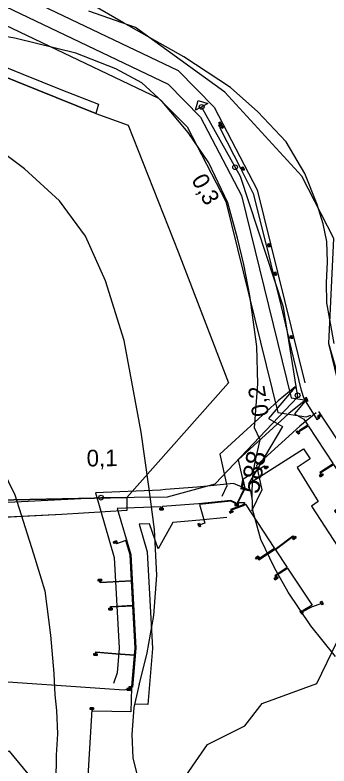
# Model space of a CAD drawing. Extents: x -709418 to -703832, y -1161719 to -1157826.
# Drawn here: x -705275.7 to -705143.5, y -1159799.2 to -1159483.1 of the extents above; entities that cross this region are included whole.
import ezdxf

# ---------------------------------------------------------------- set-up
doc = ezdxf.new("R2010")
doc.units = 0
for name, color, linetype in [('102_obvod PÚ', 7, 'Continuous'), ('103_hranice KÚ', 7, 'Continuous'), ('120_vrstevnice hlavní', 7, 'Continuous'), ('121_vrstevnice hlavní_popis', 7, 'Continuous'), ('122_vrstevnice základní', 7, 'Continuous'), ('201_orná půda_KN', 7, 'Continuous'), ('301_polní cesta_stav', 7, 'Continuous'), ('311_polní cesta_staničení', 7, 'Continuous'), ('609_LBC_stav', 7, 'Continuous'), ('611_LBK_stav', 7, 'Continuous'), ('708_el NN nadzemní a podzemní_ E.ON', 7, 'Continuous'), ('735_OP sítí TI', 7, 'Continuous'), ('Trasa-Hlavni  staniceni', 7, 'Continuous')]:
    doc.layers.add(name, color=color, linetype=linetype)

# ---------------------------------------------------------------- blocks, each defined once
blk = doc.blocks.new('Elektro - Implicitní$0$NN6301')
for points in [[(0, -0.7), (-0.7, 0)], [(-0.7, -0.7), (-0.7, 0), (0.7, 0), (0.7, -0.7)], [(-0.7, -0.7), (0.7, -0.7)], [(0, -0.7), (0.7, 0)]]:
    blk.add_lwpolyline(points)
blk = doc.blocks.new('Elektro - Implicitní$0$NN6201')
for points in [[(0.75, 0), (-0.75, 0)], [(-0.75, 0), (-0.75, -0.75)], [(0.75, -0.75), (0.75, 0)], [(-0.75, -0.75), (0.75, -0.75)], [(0.37, -0.18), (-0.38, -0.18)], [(-0.38, -0.18), (-0.38, -0.56)], [(-0.38, -0.56), (0.37, -0.56)], [(0.32, -0.23), (-0.33, -0.23)], [(-0.33, -0.23), (-0.33, -0.51)], [(-0.33, -0.51), (0.32, -0.51)], [(0.27, -0.27), (-0.28, -0.27)], [(-0.28, -0.27), (-0.28, -0.46)], [(-0.28, -0.46), (0.27, -0.46)], [(0.23, -0.32), (-0.23, -0.32)], [(-0.23, -0.32), (-0.23, -0.42)], [(-0.23, -0.42), (0.23, -0.42)], [(-0.19, -0.37), (0.19, -0.37)], [(0.23, -0.42), (0.23, -0.32)], [(0.27, -0.46), (0.27, -0.27)], [(0.32, -0.51), (0.32, -0.23)], [(0.37, -0.56), (0.37, -0.18)]]:
    blk.add_lwpolyline(points)
blk = doc.blocks.new('_kolecko-HB')
blk.add_circle((0, 0), 0.5)

msp = doc.modelspace()

# ---------------------------------------------------------------- linework, layer by layer
at = {"layer": '102_obvod PÚ'}
msp.add_lwpolyline([(-705337.11, -1159477.31), (-705321.2, -1159485.73), (-705305.28, -1159494.51), (-705288.87, -1159501.36), (-705272.46, -1159507.98), (-705256.4, -1159514.47), (-705240.56, -1159520.54), (-705241.7, -1159524.46), (-705228, -1159529.46), (-705206.95, -1159582.76), (-705185.79, -1159637.83), (-705228.59, -1159686.2), (-705228.61, -1159691.6), (-705256.06, -1159693.33), (-705338.98, -1159697.33), (-705340.61, -1159703.8), (-705368.6, -1159692.83), (-705394.93, -1159695.05), (-705422.83, -1159640.31), (-705432.68, -1159637.1), (-705471.87, -1159535.22), (-705499.42, -1159485.62), (-705524.82, -1159460.29)], dxfattribs=at)
at = {"layer": '103_hranice KÚ'}
msp.add_lwpolyline([(-705134.24, -1159654.08), (-705143.62, -1159621.36), (-705141.48, -1159577.11), (-705155, -1159550.95), (-705187.39, -1159515.59), (-705225.01, -1159488.33), (-705244.62, -1159481.43)], dxfattribs=at)
at = {"layer": '120_vrstevnice hlavní'}
for points in [[(-705223.36, -1159764.63), (-705220.12, -1159751.46), (-705217.29, -1159735.83), (-705216.04, -1159718.88), (-705216.95, -1159699.6), (-705219.35, -1159681.52), (-705222.58, -1159658.66), (-705229.69, -1159620.01), (-705237.57, -1159595), (-705246.09, -1159576.18), (-705257.01, -1159561.22), (-705271.76, -1159547.82), (-705285.35, -1159537.74), (-705305.1, -1159527.1), (-705322.99, -1159517.93), (-705362.53, -1159497), (-705381.94, -1159487.18), (-705402.79, -1159477.04)], [(-705223.39, -1159764.75), (-705225.66, -1159774.48), (-705226.57, -1159785.92), (-705226.11, -1159795.66), (-705224.32, -1159803.18), (-705221.95, -1159807.63), (-705216.68, -1159812.95), (-705208.68, -1159818.12), (-705200.49, -1159821.92), (-705193.33, -1159824), (-705183.78, -1159825.93), (-705174.04, -1159826.49), (-705160.04, -1159827.58), (-705145.01, -1159828.68), (-705126.77, -1159829.29)]]:
    msp.add_lwpolyline(points, dxfattribs=at)
msp.add_open_spline([(-705223.39, -1159764.75), (-705223.36, -1159764.63)], degree=1, dxfattribs=at)
at = {"layer": '122_vrstevnice základní'}
for points in [[(-705184.99, -1159513.55), (-705204.6, -1159500.63), (-705230, -1159486.31), (-705259.87, -1159468.99), (-705280, -1159460.17), (-705296.39, -1159454.1), (-705322.61, -1159446.57), (-705350.78, -1159437.2), (-705372.8, -1159429.22), (-705402.11, -1159420.31), (-705420.38, -1159413.38), (-705436.75, -1159405.26), (-705449.37, -1159398.53), (-705474.22, -1159384.97), (-705486.15, -1159376.87), (-705490.06, -1159372.24), (-705491.08, -1159370.18)], [(-705140.71, -1159753.08), (-705151.19, -1159740.1), (-705160.76, -1159725.96), (-705166.42, -1159715.8), (-705172.27, -1159703.79), (-705175.78, -1159691.08), (-705175.88, -1159683.03), (-705175.47, -1159675.64), (-705174.25, -1159669.85), (-705172.5, -1159661.94), (-705174.91, -1159656.77), (-705173.46, -1159638.29), (-705173.85, -1159622.6), (-705176.8, -1159601.16), (-705179.31, -1159588.1), (-705182.08, -1159577.04), (-705186.11, -1159562.15), (-705194.03, -1159545.31), (-705202.85, -1159532.45), (-705213.73, -1159519.41), (-705222.28, -1159511.55), (-705233.19, -1159505.69), (-705250.08, -1159499.11), (-705275.17, -1159493), (-705300.15, -1159488.14)], [(-705141.27, -1159621.27), (-705144.41, -1159604.18), (-705144.53, -1159595.8), (-705144.15, -1159586.91), (-705144.45, -1159578.36), (-705145.95, -1159571), (-705148.47, -1159562.78), (-705153.71, -1159549.78), (-705161.51, -1159536.41), (-705173.42, -1159523.86), (-705184.99, -1159513.55)], [(-705375.16, -1159574.07), (-705365.65, -1159584.68), (-705351.72, -1159597.22), (-705335.49, -1159608.58), (-705320.07, -1159621.01), (-705303.78, -1159637.24), (-705288.94, -1159658.17), (-705275.84, -1159685.06), (-705267.93, -1159709.84), (-705263.21, -1159725.37), (-705260.7, -1159744.04), (-705259.31, -1159760.23)], [(-705259.3, -1159760.39), (-705258.95, -1159769.2), (-705258.3, -1159775.86), (-705257.84, -1159785.59), (-705258.44, -1159794.64), (-705258.5, -1159805.91), (-705255.64, -1159815.31), (-705253.89, -1159818.36)]]:
    msp.add_lwpolyline(points, dxfattribs=at)
msp.add_open_spline([(-705259.31, -1159760.23), (-705259.3, -1159760.39)], degree=1, dxfattribs=at)
at = {"layer": '201_orná půda_KN'}
for p, q in [((-705306.42, -1159498.51), (-705241.7, -1159524.46)), ((-705241.7, -1159524.46), (-705306.42, -1159498.51)), ((-705288.87, -1159501.36), (-705272.46, -1159507.98)), ((-705272.46, -1159507.98), (-705256.4, -1159514.47)), ((-705256.4, -1159514.47), (-705240.56, -1159520.54)), ((-705240.56, -1159520.54), (-705241.7, -1159524.46)), ((-705241.7, -1159524.46), (-705228, -1159529.46)), ((-705228, -1159529.46), (-705206.95, -1159582.76)), ((-705206.95, -1159582.76), (-705185.79, -1159637.83)), ((-705185.79, -1159637.83), (-705228.59, -1159686.2)), ((-705228.59, -1159686.2), (-705288.14, -1159687.37)), ((-705288.14, -1159687.37), (-705228.59, -1159686.2)), ((-705228.59, -1159686.2), (-705228.61, -1159691.6)), ((-705228.61, -1159691.6), (-705256.06, -1159693.33)), ((-705256.06, -1159693.33), (-705338.98, -1159697.33))]:
    msp.add_line(p, q, dxfattribs=at)
at = {"layer": '301_polní cesta_stav'}
msp.add_lwpolyline([(-705338.51, -1159697.31), (-705319.15, -1159695.45), (-705292.64, -1159688.75), (-705239.63, -1159686.2), (-705211.53, -1159685.88), (-705191.42, -1159680.45), (-705156.61, -1159643.75), (-705162.63, -1159605.98), (-705180.83, -1159551.09), (-705197.12, -1159521.73)], dxfattribs=at)
at = {"layer": '311_polní cesta_staničení'}
msp.add_lwpolyline([(-705199.75, -1159523.16), (-705198.55, -1159519.09), (-705194.48, -1159520.29), (-705199.75, -1159523.16)], dxfattribs=at)
at = {"layer": '609_LBC_stav'}
msp.add_lwpolyline([(-705517, -1160362.3), (-705369.22, -1160210.37), (-705299.31, -1160130.26), (-705201.9, -1160128.94), (-705159.78, -1160035.52), (-705055.56, -1159909.96), (-705073.99, -1159896.8), (-705110.85, -1159883.64), (-705179.3, -1159879.69), (-705206.94, -1159849.43), (-705259.6, -1159815.22), (-705278.03, -1159792.85), (-705321.47, -1159804.69), (-705388.6, -1159766.54), (-705550.51, -1159977.06), (-705526.72, -1159995.51), (-705491.92, -1160067.67), (-705561.96, -1160193.15), (-705583.87, -1160190.33), (-705632.13, -1160220.48), (-705677.11, -1160208.39), (-705689.77, -1160240.43), (-705690.96, -1160281.19), (-705760.43, -1160283.48)], dxfattribs=at)
at = {"layer": '611_LBK_stav'}
msp.add_lwpolyline([(-705259.6, -1159815.22), (-705219.16, -1159825.55), (-705194.62, -1159790.06), (-705178.95, -1159782.23), (-705171.64, -1159772.84), (-705148.67, -1159764.49), (-705133.52, -1159733.17), (-705116.29, -1159722.73), (-705107.2, -1159710.55), (-705119.32, -1159704.91), (-705115.37, -1159697.5), (-705124.32, -1159679.92), (-705129.91, -1159677.26), (-705143.62, -1159621.36), (-705141.48, -1159577.11), (-705155, -1159550.95), (-705187.39, -1159515.59), (-705225.01, -1159488.33)], dxfattribs=at)
at = {"layer": '708_el NN nadzemní a podzemní_ E.ON'}
for points in [[(-705466.35, -1159394.29), (-705417.95, -1159425.05), (-705391.08, -1159429.47), (-705369.86, -1159436.43), (-705211.18, -1159512.22), (-705197.54, -1159525.99), (-705180.35, -1159559.09), (-705159.37, -1159644.15), (-705153.76, -1159644.98), (-705153.4, -1159644.86)], [(-705153.51, -1159644.63), (-705153.92, -1159644.57), (-705155.14, -1159641.12), (-705160.37, -1159619.08), (-705159.64, -1159618.75), (-705160.44, -1159618.79), (-705164.24, -1159602.78), (-705166.81, -1159592.33), (-705166.35, -1159592.06), (-705166.88, -1159592.03), (-705169.74, -1159580.38), (-705169.06, -1159580.06), (-705169.81, -1159580.09), (-705175.09, -1159558.59), (-705180.35, -1159548.25), (-705179.98, -1159547.89), (-705180.48, -1159547.98), (-705189.3, -1159530.62), (-705188.82, -1159530.21), (-705189.44, -1159530.36), (-705189.91, -1159529.43), (-705189.53, -1159529.04)], [(-705153.31, -1159645.05), (-705160.37, -1159650.75), (-705181.75, -1159670.29), (-705179.1, -1159682.11), (-705182.38, -1159688.8)], [(-705153.19, -1159645.32), (-705153.62, -1159645.67), (-705158.09, -1159650.96), (-705154.07, -1159653.21), (-705152.41, -1159655.73), (-705155.95, -1159657.99), (-705156.29, -1159658.56), (-705152.25, -1159655.98), (-705141.77, -1159671.94), (-705147.4, -1159675.63), (-705146.9, -1159676.44), (-705146.92, -1159675.67), (-705141.61, -1159672.19), (-705132.49, -1159686.08), (-705141.2, -1159691.78), (-705140.63, -1159692.66), (-705140.72, -1159691.84), (-705132.33, -1159686.33), (-705123.68, -1159699.51), (-705131.88, -1159705.22), (-705131.71, -1159705.83)], [(-705153.09, -1159645.54), (-705153.29, -1159645.81), (-705148.63, -1159653.31), (-705147.46, -1159652.6), (-705147.38, -1159652.17)], [(-705182.06, -1159688.82), (-705178.78, -1159682.15), (-705179.64, -1159678.33), (-705170.64, -1159672.8), (-705169.99, -1159673.1)], [(-705182.6, -1159688.79), (-705182.68, -1159688.34), (-705184.83, -1159687.41), (-705198.43, -1159688.78), (-705211.78, -1159689.78), (-705213.66, -1159689.97), (-705214.02, -1159690.63), (-705214.24, -1159690.01), (-705232.64, -1159690.78), (-705226.95, -1159710.17), (-705224.88, -1159749.62), (-705226.24, -1159766.03), (-705227.34, -1159765.99), (-705227.52, -1159766.56)], [(-705182.82, -1159688.77), (-705183.13, -1159688.48), (-705184.88, -1159687.72), (-705198.04, -1159689.06), (-705195.81, -1159696.89), (-705197.8, -1159697.67)], [(-705181.77, -1159688.82), (-705181.63, -1159688.48), (-705181.18, -1159688.29), (-705179.17, -1159688.24), (-705178.89, -1159688.67), (-705179.69, -1159689.2), (-705184.93, -1159691.26), (-705184.71, -1159691.84), (-705184.43, -1159691.39), (-705179.55, -1159689.46), (-705178.72, -1159688.92), (-705166.4, -1159707.61), (-705172.99, -1159711.96), (-705173.44, -1159711.77), (-705173.04, -1159712.34), (-705166.23, -1159707.86), (-705158.71, -1159702.34), (-705158.29, -1159702.85), (-705158.74, -1159702.74), (-705166.06, -1159708.11), (-705161.12, -1159715.6), (-705166.37, -1159719.06), (-705165.94, -1159719.78), (-705165.96, -1159719.15), (-705160.96, -1159715.85), (-705150.63, -1159731.51), (-705154.4, -1159733.76), (-705154.8, -1159734.3)], [(-705227.85, -1159766.55), (-705227.62, -1159765.67), (-705226.51, -1159765.72), (-705225.43, -1159752.68), (-705233.22, -1159752.04), (-705241.45, -1159751.4), (-705241.81, -1159751.87), (-705241.66, -1159751.09), (-705233.2, -1159751.74), (-705225.41, -1159752.38), (-705225.18, -1159749.61), (-705226.11, -1159731.82), (-705235.2, -1159732.29), (-705235.48, -1159732.74), (-705235.47, -1159732.01), (-705226.13, -1159731.52), (-705226.66, -1159721.42), (-705239.88, -1159722.11), (-705239.94, -1159721.34), (-705239.6, -1159721.79), (-705226.68, -1159721.12), (-705227.25, -1159710.22), (-705229.01, -1159704.21), (-705233.03, -1159705.63), (-705233.41, -1159705.24)], [(-705154.8, -1159734.3), (-705150.4, -1159732.07), (-705146.77, -1159730.76)], [(-705228.63, -1159766.91), (-705229.71, -1159767.24), (-705295.16, -1159762.77), (-705300.36, -1159766.38)], [(-705227.22, -1159766.57), (-705227.05, -1159766.3), (-705226.6, -1159766.32), (-705226.95, -1159776.33), (-705242.94, -1159776.06), (-705243.42, -1159775.34), (-705245.17, -1159805.89)]]:
    msp.add_lwpolyline(points, dxfattribs=at)
at = {"layer": '735_OP sítí TI'}
for points in [[(-705462.59, -1159388.39), (-705415.4, -1159418.37), (-705389.41, -1159422.65), (-705367.25, -1159429.92), (-705207.06, -1159506.43), (-705191.82, -1159521.82), (-705173.75, -1159556.6), (-705153.71, -1159637.87)], [(-705470.1, -1159400.2), (-705420.5, -1159431.73), (-705392.75, -1159436.29), (-705372.47, -1159442.94), (-705215.3, -1159518.01), (-705203.26, -1159530.16), (-705186.95, -1159561.58), (-705165.04, -1159650.38), (-705153.13, -1159652.15), (-705151.19, -1159651.5)], [(-705157.71, -1159639.6), (-705164.93, -1159645.44), (-705189.47, -1159667.86), (-705186.47, -1159681.24), (-705188.67, -1159685.72)], [(-705157.61, -1159639.89), (-705158.55, -1159640.65), (-705168.91, -1159652.92), (-705163.04, -1159656.21), (-705177.44, -1159680.35), (-705154.31, -1159665.6), (-705151.47, -1159669.93), (-705156.96, -1159673.54), (-705148.02, -1159687.88), (-705150.86, -1159689.74), (-705130.27, -1159721.53), (-705131.27, -1159712.82)], [(-705148.91, -1159650.5), (-705155.81, -1159656.06), (-705174.03, -1159672.72), (-705171.73, -1159682.98), (-705176.09, -1159691.88)], [(-705147.88, -1159649.88), (-705145.19, -1159653.98), (-705132.08, -1159673.95), (-705132.08, -1159673.95), (-705122.8, -1159688.1), (-705122.8, -1159688.1), (-705114.09, -1159701.36), (-705125.73, -1159709.47)], [(-705175.71, -1159687.51), (-705176.48, -1159683.4), (-705183.72, -1159680.26), (-705199.05, -1159681.8), (-705212.39, -1159682.81), (-705214.42, -1159683.01), (-705241.88, -1159684.16), (-705233.9, -1159711.35), (-705231.9, -1159749.51), (-705232.75, -1159759.92), (-705234.19, -1159764.44)], [(-705186.48, -1159694.61), (-705197.82, -1159695.75), (-705209.31, -1159696.61), (-705215.38, -1159707.74), (-705219.11, -1159697.22), (-705223.4, -1159697.4), (-705220, -1159708.99), (-705217.86, -1159749.73), (-705219.81, -1159773.32), (-705225.01, -1159773.09)]]:
    msp.add_lwpolyline(points, dxfattribs=at)

# ---------------------------------------------------------------- block references
at = {"layer": '708_el NN nadzemní a podzemní_ E.ON'}
for name, p, rotation in [('Elektro - Implicitní$0$NN6301', (-705189.53, -1159529.04), 119.68557779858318), ('Elektro - Implicitní$0$NN6301', (-705188.82, -1159530.21), 119.58653057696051), ('Elektro - Implicitní$0$NN6301', (-705179.98, -1159547.89), 118.92464441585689), ('Elektro - Implicitní$0$NN6301', (-705169.06, -1159580.06), 103.30584442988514), ('Elektro - Implicitní$0$NN6301', (-705166.35, -1159592.06), 103.51784719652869), ('Elektro - Implicitní$0$NN6301', (-705159.64, -1159618.75), 103.5178471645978), ('Elektro - Implicitní$0$NN6201', (-705153.31, -1159645.05), 115.3412278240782), ('Elektro - Implicitní$0$NN6301', (-705147.38, -1159652.17), -145.76263333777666), ('Elektro - Implicitní$0$NN6301', (-705156.29, -1159658.56), -47.21597508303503), ('Elektro - Implicitní$0$NN6301', (-705169.99, -1159673.1), 26.672438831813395), ('Elektro - Implicitní$0$NN6301', (-705146.9, -1159676.44), 32.37411667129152), ('Elektro - Implicitní$0$NN6301', (-705214.02, -1159690.63), 3.071586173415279), ('Elektro - Implicitní$0$NN6301', (-705184.71, -1159691.84), 23.271108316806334), ('Elektro - Implicitní$0$NN6201', (-705182.38, -1159688.8), -3.4101721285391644), ('Elektro - Implicitní$0$NN6301', (-705197.8, -1159697.67), -71.0167167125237), ('Elektro - Implicitní$0$NN6301', (-705158.29, -1159702.85), 34.082927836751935), ('Elektro - Implicitní$0$NN6301', (-705233.41, -1159705.24), -161.2546471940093), ('Elektro - Implicitní$0$NN6301', (-705173.44, -1159711.77), -145.34731939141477), ('Elektro - Implicitní$0$NN6301', (-705165.94, -1159719.78), 33.78308332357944), ('Elektro - Implicitní$0$NN6301', (-705239.94, -1159721.34), -175.58081111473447), ('Elektro - Implicitní$0$NN6301', (-705235.48, -1159732.74), 3.0897582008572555), ('Elektro - Implicitní$0$NN6301', (-705146.77, -1159730.76), 123.43011115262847), ('Elektro - Implicitní$0$NN6301', (-705154.8, -1159734.3), -52.983838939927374), ('Elektro - Implicitní$0$NN6301', (-705241.81, -1159751.87), -1.2103167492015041), ('Elektro - Implicitní$0$NN6201', (-705227.85, -1159766.55), -2.1549582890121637), ('Elektro - Implicitní$0$NN6301', (-705243.42, -1159775.34), 178.82357763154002)]:
    msp.add_blockref(name, p, dxfattribs=dict(at, rotation=rotation))
at = {"layer": 'Trasa-Hlavni  staniceni'}
for p, xscale, yscale, rotation in [((-705197.12, -1159521.73), 1.9999999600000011, 1.9999999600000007, 119.0168780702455), ((-705183.04, -1159547.12), 1.9999999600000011, 1.9999999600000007, 119.0168780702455), ((-705156.71, -1159643.14), 1.999999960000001, 1.9999999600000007, 99.05815419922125), ((-705239.49, -1159686.2), 1.9999999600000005, 1.999999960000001, 0.6506330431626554)]:
    msp.add_blockref('_kolecko-HB', p, dxfattribs=dict(at, xscale=xscale, yscale=yscale, rotation=rotation))

# ---------------------------------------------------------------- texts
at = {"layer": '121_vrstevnice hlavní_popis'}
msp.add_text('588', height=8, rotation=79.7997, dxfattribs=at).set_placement((-705173.13, -1159684.94))
at = {"layer": 'Trasa-Hlavni  staniceni'}
for s, height, rotation, p in [('0,3', 0.000000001, 299.0169, (-705210.63, -1159530.36)), ('0,3', 7, 299.0169, (-705201.64, -1159552.38)), ('0,2', 7, 99.0582, (-705168.72, -1159651.53)), ('0,1', 7, 0.6506, (-705245.52, -1159673.08))]:
    msp.add_text(s, height=height, rotation=rotation, dxfattribs=at).set_placement(p)

doc.saveas('drawing.dxf')
